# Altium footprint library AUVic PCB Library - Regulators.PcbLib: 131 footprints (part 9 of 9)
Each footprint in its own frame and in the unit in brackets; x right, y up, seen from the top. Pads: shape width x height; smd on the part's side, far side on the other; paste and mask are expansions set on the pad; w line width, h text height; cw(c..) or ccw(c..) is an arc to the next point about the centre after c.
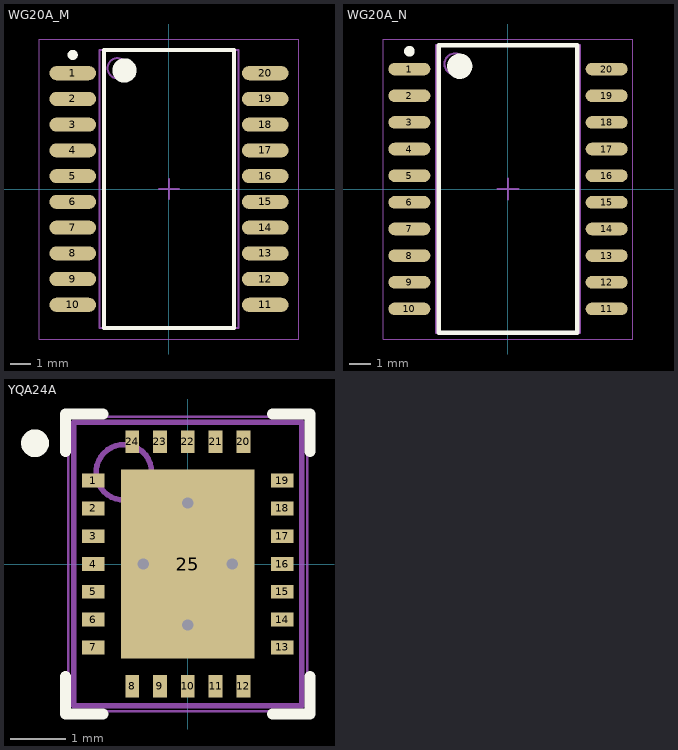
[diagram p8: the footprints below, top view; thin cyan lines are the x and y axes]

## WG20A_M [mm] "CERPACK, 20-Leads, Body 26.6x9.4mm, Pitch 1.27mm, IPC Low Density"
height 2.5
pads (20):
  oval 2.3x0.7 smd: 1(-4.75,5.715) 2(-4.75,4.445) 3(-4.75,3.175) 4(-4.75,1.905) 5(-4.75,0.635) 6(-4.75,-0.635) 7(-4.75,-1.905) 8(-4.75,-3.175) 9(-4.75,-4.445) 10(-4.75,-5.715) 11(4.75,-5.715) 12(4.75,-4.445) 13(4.75,-3.175) 14(4.75,-1.905) 15(4.75,-0.635) 16(4.75,0.635) 17(4.75,1.905) 18(4.75,3.175) 19(4.75,4.445) 20(4.75,5.715)
Top Overlay:
  circle w0.25: c-4.75,6.615 r0.125
  circle w0.6: c-2.2,5.85 r0.3
  lines w0.2: -3.2,-6.85 -3.2,6.85 3.2,6.85 3.2,-6.85 -3.2,-6.85
Mechanical 13:
  circle w0.1: c-2.53,5.96 r0.5
  lines w0.1: -3.43,-6.86 -3.43,6.86 3.43,6.86 3.43,-6.86 -3.43,-6.86
Mechanical 15:
  lines w0.05: -6.4,-7.4 -6.4,7.4 6.4,7.4 6.4,-7.4 -6.4,-7.4
  lines w0.1: -0.5,0 0.5,0 ; 0,-0.5 0,0.5
3D body: height 2.5, standoff 0.1, extent -3.43,-6.86 3.43,6.86

## WG20A_N [mm] "CERPACK, 20-Leads, Body 26.6x9.4mm, Pitch 1.27mm, IPC Medium Density"
height 2.5
pads (20):
  oval 2x0.6 smd: 1(-4.7,5.715) 2(-4.7,4.445) 3(-4.7,3.175) 4(-4.7,1.905) 5(-4.7,0.635) 6(-4.7,-0.635) 7(-4.7,-1.905) 8(-4.7,-3.175) 9(-4.7,-4.445) 10(-4.7,-5.715) 11(4.7,-5.715) 12(4.7,-4.445) 13(4.7,-3.175) 14(4.7,-1.905) 15(4.7,-0.635) 16(4.7,0.635) 17(4.7,1.905) 18(4.7,3.175) 19(4.7,4.445) 20(4.7,5.715)
Top Overlay:
  circle w0.25: c-4.7,6.565 r0.125
  circle w0.6: c-2.3,5.85 r0.3
  lines w0.2: -3.3,-6.85 -3.3,6.85 3.3,6.85 3.3,-6.85 -3.3,-6.85
Mechanical 13:
  circle w0.1: c-2.53,5.96 r0.5
  lines w0.1: -3.43,-6.86 -3.43,6.86 3.43,6.86 3.43,-6.86 -3.43,-6.86
Mechanical 15:
  lines w0.05: -5.95,-7.15 -5.95,7.15 5.95,7.15 5.95,-7.15 -5.95,-7.15
  lines w0.1: -0.5,0 0.5,0 ; 0,-0.5 0,0.5
3D body: height 2.5, standoff 0.1, extent -3.43,-6.86 3.43,6.86

## YQA24A [mm] "PQFN, 24-Leads, Body 5x4mm, Pitch 0.5mm, NSC Recommended"
height 0.8
pads (25):
  rect 0.4x0.25 smd paste-0.2 mask+0.051: 1(-1.7,1.5) 2(-1.7,1) 3(-1.7,0.5) 4(-1.7,0) 5(-1.7,-0.5) 6(-1.7,-1) 7(-1.7,-1.5) 13(1.7,-1.5) 14(1.7,-1) 15(1.7,-0.5) 16(1.7,0) 17(1.7,0.5) 18(1.7,1) 19(1.7,1.5)
  rect 0.25x0.4 smd paste-0.2 mask+0.051: 8(-1,-2.2) 9(-0.5,-2.2) 10(0,-2.2) 11(0.5,-2.2) 12(1,-2.2) 20(1,2.2) 21(0.5,2.2) 22(0,2.2) 23(-0.5,2.2) 24(-1,2.2)
  rect 2.4x3.4 smd paste-1.2 mask+0.051: 25(0,0)
via -0.8,0 diameter 0.5 hole 0.2
via 0,-1.1 diameter 0.5 hole 0.2
via 0,1.1 diameter 0.5 hole 0.2
via 0.8,0 diameter 0.5 hole 0.2
Top Overlay:
  circle w0.25: c-2.75,2.175 r0.125
  lines w0.2: -2.2,-2.025 -2.2,-2.7 -1.525,-2.7 ; -2.2,2.025 -2.2,2.7 -1.525,2.7 ; 1.525,-2.7 2.2,-2.7 2.2,-2.025 ; 1.525,2.7 2.2,2.7 2.2,2.025
Top Paste:
  rectangle: 0.875,2.1 1.125,2.5
  rectangle: 0.375,2.1 0.625,2.5
  rectangle: -0.125,2.1 0.125,2.5
  rectangle: -0.625,2.1 -0.375,2.5
  region: -0.875,2.5 -1.125,2.5 -1.125,2.1 -0.875,2.1
  region: -0.875,-2.1 -1.125,-2.1 -1.125,-2.5 -0.875,-2.5
  rectangle: -0.625,-2.5 -0.375,-2.1
  rectangle: -0.125,-2.5 0.125,-2.1
  rectangle: 0.375,-2.5 0.625,-2.1
  region: 2,-1.375 1.6,-1.375 1.6,-1.625 2,-1.625
  region: 2,-0.875 1.6,-0.875 1.6,-1.125 2,-1.125
  region: 2,-0.375 1.6,-0.375 1.6,-0.625 2,-0.625
  region: 2,0.125 1.6,0.125 1.6,-0.125 2,-0.125
  region: 2,0.625 1.6,0.625 1.6,0.375 2,0.375
  region: 2,1.125 1.6,1.125 1.6,0.875 2,0.875
  region: 2,1.625 1.6,1.625 1.6,1.375 2,1.375
  rectangle: -2,1.375 -1.6,1.625
  rectangle: 0.15,0.15 1.1,1.6
  region: -0.15,1.6 -1.1,1.6 -1.1,0.15 -0.15,0.15
  region: -0.15,-0.15 -1.1,-0.15 -1.1,-1.6 -0.15,-1.6
  rectangle: 0.15,-1.6 1.1,-0.15
  rectangle: -2,0.875 -1.6,1.125
  rectangle: -2,0.375 -1.6,0.625
  rectangle: -2,-0.125 -1.6,0.125
  rectangle: -2,-0.625 -1.6,-0.375
  rectangle: -2,-1.125 -1.6,-0.875
  rectangle: -2,-1.625 -1.6,-1.375
  rectangle: 0.875,-2.5 1.125,-2.1
Mechanical 13:
  circle w0.1: c-1.15,1.65 r0.5
  lines w0.1: -2.05,-2.55 2.05,-2.55 2.05,2.55 -2.05,2.55 -2.05,-2.55
Mechanical 15:
  lines w0.05: -2.15,-2.65 2.15,-2.65 2.15,2.65 -2.15,2.65 -2.15,-2.65
  lines w0.1: -0.5,0 0.5,0 ; 0,-0.5 0,0.5
3D body: height 0.8, standoff 0, extent -2.05,-2.55 2.05,2.55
